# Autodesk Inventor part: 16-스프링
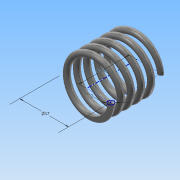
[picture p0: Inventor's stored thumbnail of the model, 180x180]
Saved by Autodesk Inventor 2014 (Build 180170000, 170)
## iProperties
Created: 2016-01
Part Number: 16-스프링
Material: 강철, 탄소
Document SubType Name: Modeling
Designer: Administrator
Density: 7.87 g/cm^3
Appearance: 반연마
Mass: 6.44239 g
Surface Area: 16.6857 cm^2
Volume: 0.818602 cm^3
Author: Administrator
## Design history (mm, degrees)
sketch "스케치1"
  geometry: L1 (0, 0)-(8.5, 0); L2 (8.5, 0)-(8.5, 17.5); L3 (8.5, 17.5)-(0, 17.5); L4 (0, 17.5)-(0, 0); C1 r 1 at (8.5, 0)
  constraints: 8 end point, 2 parallel, 1 centre point, 1 coincident, 1 horizontal, 1 perpendicular
  dimensions: "d0" = 17 diameter of L2 L4; "d1" = 17.5 distance of L3.end L1.start (derived); "d2" = 2 diameter of C1
feature "코일1" sketch "스케치1" pitch "d3" = 10; turns "d5" = 5; dims "d4" = 17.5 (= d1), "d6" = 0, angle "d7" = 90 deg, angle "d8" = 90 deg, "d9" = 0, "d10" = 0
node "작업 평면1"
sketch "스케치2"
  geometry: L1 (-9.5, 0)-(-7.5, 0) reference; 1 further point
  constraints: 1 horizontal alignment
extrude "돌출1" cut sketch "스케치2" stored distance "d12" = 10; taper "d13" = 0 deg
node "작업 평면2"
sketch "스케치3"
  geometry: L1 (-7.5, 0)-(-9.5, 0) reference; 1 further point
  constraints: 1 horizontal alignment
extrude "돌출2" cut sketch "스케치3" stored distance "d15" = 10; taper "d16" = 0 deg
node "솔리드1"
node "절단 모서리 투영1"
node "절단 모서리 투영2"
other parameters: "d11" = 0, "d14" = 17.5 (= d1)
